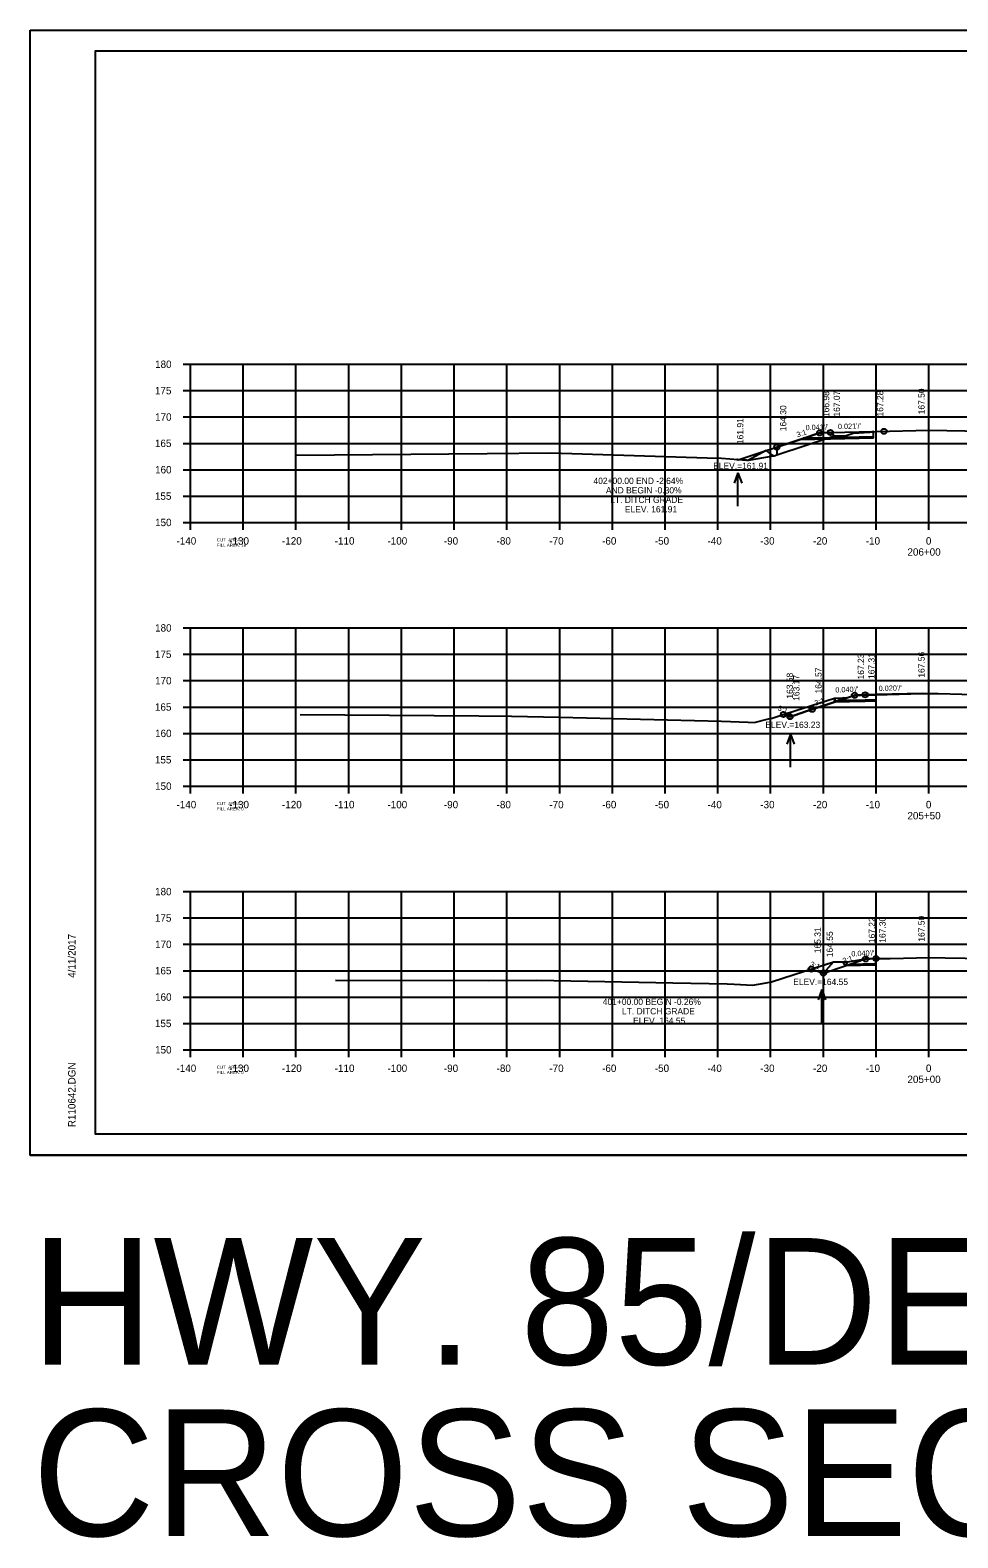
# Model space of a CAD drawing. Extents: x 1368503 to 1373085, y 379840 to 381833.
# Drawn here: x 1368502.7 to 1368678.6, y 379840.1 to 380126 of the extents above; entities that cross this region are included whole.
import ezdxf

# ---------------------------------------------------------------- set-up
doc = ezdxf.new("R2010")
doc.units = 0
for name, color, linetype in [('S_BRIDGE', 7, 'Continuous'), ('S_EDGE_PAVEMENT', 7, 'Continuous'), ('S_GRAVEL_ROAD', 7, 'Continuous'), ('S_MISC_BOUNDARY', 7, 'Continuous'), ('S_OBSCURES', 7, 'Continuous'), ('S_PHOTO_CENTERS', 7, 'Continuous'), ('S_PHOTO_NOTES', 7, 'Continuous'), ('S_RDW_PT_SYM', 7, 'Continuous'), ('S_SHOULDER', 7, 'Continuous'), ('S_STREAM_ANNOT', 7, 'Continuous'), ('S_TRAILS', 7, 'Continuous'), ('S_TRAILS_ANNOT', 7, 'Continuous'), ('S_TREE', 7, 'Continuous')]:
    doc.layers.add(name, color=color, linetype=linetype)

msp = doc.modelspace()

# ---------------------------------------------------------------- linework, layer by layer
at = {"layer": 'S_BRIDGE'}
for p, q in [((1368515.06, 380122.15), (1368831.24, 380122.15)), ((1368515.06, 379916.69), (1368515.06, 380122.15)), ((1368667.58, 380121.89), (1368667.58, 380121.89)), ((1368667.58, 380121.89), (1368667.58, 380121.89)), ((1368515.06, 379916.69), (1368515.06, 379916.69)), ((1368831.24, 379916.69), (1368515.06, 379916.69))]:
    msp.add_line(p, q, dxfattribs=at)
at = {"layer": 'S_EDGE_PAVEMENT'}
for p, q in [((1368531.66, 380062.69), (1368533.06, 380062.69)), ((1368533.06, 380032.69), (1368533.06, 380062.69)), ((1368531.66, 380057.69), (1368533.06, 380057.69)), ((1368531.66, 380052.69), (1368533.06, 380052.69)), ((1368531.66, 380047.69), (1368533.06, 380047.69)), ((1368531.66, 380042.69), (1368533.06, 380042.69)), ((1368531.66, 380037.69), (1368533.06, 380037.69)), ((1368531.66, 380032.69), (1368533.06, 380032.69)), ((1368533.06, 380032.69), (1368813.06, 380032.69)), ((1368533.06, 380031.29), (1368533.06, 380032.69)), ((1368543.06, 380031.29), (1368543.06, 380032.69)), ((1368553.06, 380031.29), (1368553.06, 380032.69)), ((1368563.06, 380031.29), (1368563.06, 380032.69)), ((1368573.06, 380031.29), (1368573.06, 380032.69)), ((1368583.06, 380031.29), (1368583.06, 380032.69)), ((1368593.06, 380031.29), (1368593.06, 380032.69)), ((1368603.06, 380031.29), (1368603.06, 380032.69)), ((1368613.06, 380031.29), (1368613.06, 380032.69)), ((1368623.06, 380031.29), (1368623.06, 380032.69)), ((1368633.06, 380031.29), (1368633.06, 380032.69)), ((1368643.06, 380031.29), (1368643.06, 380032.69)), ((1368653.06, 380031.29), (1368653.06, 380032.69)), ((1368663.06, 380031.29), (1368663.06, 380032.69)), ((1368673.06, 380031.29), (1368673.06, 380032.69)), ((1368531.66, 380012.69), (1368533.06, 380012.69)), ((1368533.06, 379982.69), (1368533.06, 380012.69)), ((1368531.66, 380007.69), (1368533.06, 380007.69)), ((1368531.66, 380002.69), (1368533.06, 380002.69)), ((1368531.66, 379997.69), (1368533.06, 379997.69)), ((1368531.66, 379992.69), (1368533.06, 379992.69)), ((1368531.66, 379987.69), (1368533.06, 379987.69)), ((1368531.66, 379982.69), (1368533.06, 379982.69)), ((1368533.06, 379982.69), (1368813.06, 379982.69)), ((1368533.06, 379981.29), (1368533.06, 379982.69)), ((1368543.06, 379981.29), (1368543.06, 379982.69)), ((1368553.06, 379981.29), (1368553.06, 379982.69)), ((1368563.06, 379981.29), (1368563.06, 379982.69)), ((1368573.06, 379981.29), (1368573.06, 379982.69)), ((1368583.06, 379981.29), (1368583.06, 379982.69)), ((1368593.06, 379981.29), (1368593.06, 379982.69)), ((1368603.06, 379981.29), (1368603.06, 379982.69)), ((1368613.06, 379981.29), (1368613.06, 379982.69)), ((1368623.06, 379981.29), (1368623.06, 379982.69)), ((1368633.06, 379981.29), (1368633.06, 379982.69)), ((1368643.06, 379981.29), (1368643.06, 379982.69)), ((1368653.06, 379981.29), (1368653.06, 379982.69)), ((1368663.06, 379981.29), (1368663.06, 379982.69)), ((1368673.06, 379981.29), (1368673.06, 379982.69)), ((1368531.66, 379962.69), (1368533.06, 379962.69)), ((1368533.06, 379932.69), (1368533.06, 379962.69)), ((1368531.66, 379957.69), (1368533.06, 379957.69)), ((1368531.66, 379952.69), (1368533.06, 379952.69)), ((1368531.66, 379947.69), (1368533.06, 379947.69)), ((1368531.66, 379942.69), (1368533.06, 379942.69)), ((1368531.66, 379937.69), (1368533.06, 379937.69)), ((1368531.66, 379932.69), (1368533.06, 379932.69)), ((1368533.06, 379932.69), (1368813.06, 379932.69)), ((1368533.06, 379931.29), (1368533.06, 379932.69)), ((1368543.06, 379931.29), (1368543.06, 379932.69)), ((1368553.06, 379931.29), (1368553.06, 379932.69)), ((1368563.06, 379931.29), (1368563.06, 379932.69)), ((1368573.06, 379931.29), (1368573.06, 379932.69)), ((1368583.06, 379931.29), (1368583.06, 379932.69)), ((1368593.06, 379931.29), (1368593.06, 379932.69)), ((1368603.06, 379931.29), (1368603.06, 379932.69)), ((1368613.06, 379931.29), (1368613.06, 379932.69)), ((1368623.06, 379931.29), (1368623.06, 379932.69)), ((1368633.06, 379931.29), (1368633.06, 379932.69)), ((1368643.06, 379931.29), (1368643.06, 379932.69)), ((1368653.06, 379931.29), (1368653.06, 379932.69)), ((1368663.06, 379931.29), (1368663.06, 379932.69)), ((1368673.06, 379931.29), (1368673.06, 379932.69))]:
    msp.add_line(p, q, dxfattribs=at)
at = {"layer": 'S_GRAVEL_ROAD'}
for p, q in [((1368636.87, 380042.08), (1368636.17, 380040.15)), ((1368636.87, 380035.79), (1368636.87, 380042.08)), ((1368636.87, 380042.08), (1368637.57, 380040.15)), ((1368646.8, 379992.54), (1368646.1, 379990.62)), ((1368646.8, 379986.26), (1368646.8, 379992.54)), ((1368646.8, 379992.54), (1368647.5, 379990.62)), ((1368652.75, 379944.11), (1368652.05, 379942.19)), ((1368652.75, 379937.83), (1368652.75, 379944.11)), ((1368652.75, 379944.11), (1368653.45, 379942.19))]:
    msp.add_line(p, q, dxfattribs=at)
at = {"layer": 'S_MISC_BOUNDARY'}
for points in [[(1368553.12, 380045.44), (1368589.33, 380045.77), (1368601.36, 380045.92), (1368631, 380044.95), (1368633.74, 380044.86), (1368638.49, 380044.53), (1368638.85, 380044.51), (1368638.86, 380044.51), (1368643.63, 380045.32), (1368643.71, 380045.34), (1368644.22, 380045.51), (1368655.16, 380049.14), (1368656.51, 380049.12), (1368657.09, 380049.12), (1368657.26, 380049.13), (1368657.4, 380049.18), (1368658.68, 380049.59), (1368661.9, 380049.83), (1368662.56, 380049.9), (1368663.09, 380049.91), (1368673.13, 380050.19), (1368683.23, 380050)], [(1368553.88, 379996.27), (1368587.76, 379996.01), (1368593.95, 379995.98), (1368603.01, 379995.75), (1368633.77, 379995), (1368638.78, 379994.83), (1368639.91, 379994.78), (1368642.67, 379995.43), (1368643.32, 379995.56), (1368646.23, 379996.52), (1368655.15, 379999.36), (1368656.88, 379999.44), (1368657.38, 379999.44), (1368658.46, 379999.73), (1368658.94, 379999.85), (1368660.17, 379999.91), (1368662.95, 380000.02), (1368671.95, 380000.23), (1368673.36, 380000.26), (1368674.81, 380000.23), (1368683.78, 380000.03)], [(1368560.55, 379945.87), (1368589.57, 379945.84), (1368598.71, 379945.87), (1368624.54, 379945.37), (1368634.81, 379945.2), (1368636.13, 379945.13), (1368639.7, 379944.97), (1368642.21, 379945.41), (1368643.23, 379945.56), (1368647.5, 379946.94), (1368655.01, 379949.38), (1368656.69, 379949.37), (1368657.63, 379949.36), (1368659.94, 379949.75), (1368660.37, 379949.83), (1368660.89, 379949.85), (1368663.01, 379949.98), (1368665.73, 379950.03), (1368673.22, 379950.19), (1368676.14, 379950.14), (1368683.74, 379949.99)]]:
    msp.add_lwpolyline(points, dxfattribs=at)
at = {"layer": 'S_OBSCURES'}
for points in [[(1368662.56, 380048.68), (1368654.4, 380048.51), (1368648.44, 380048.38)], [(1368662.56, 380048.93), (1368654.4, 380048.76), (1368649.25, 380048.65)], [(1368663.06, 379998.8), (1368660.98, 379998.75), (1368655.09, 379998.64)], [(1368663.06, 379999.05), (1368660.98, 379999), (1368655.89, 379998.9)], [(1368663.01, 379948.74), (1368657.2, 379948.62)], [(1368663.01, 379948.99), (1368658, 379948.89)]]:
    msp.add_lwpolyline(points, dxfattribs=at)
at = {"layer": 'S_PHOTO_CENTERS'}
for p, q in [((1368533.06, 380062.69), (1368813.06, 380062.69)), ((1368533.06, 380032.69), (1368533.06, 380062.69)), ((1368543.06, 380032.69), (1368543.06, 380062.69)), ((1368553.06, 380032.69), (1368553.06, 380062.69)), ((1368563.06, 380032.69), (1368563.06, 380062.69)), ((1368573.06, 380032.69), (1368573.06, 380062.69)), ((1368583.06, 380032.69), (1368583.06, 380062.69)), ((1368593.06, 380032.69), (1368593.06, 380062.69)), ((1368603.06, 380032.69), (1368603.06, 380062.69)), ((1368613.06, 380032.69), (1368613.06, 380062.69)), ((1368623.06, 380032.69), (1368623.06, 380062.69)), ((1368633.06, 380032.69), (1368633.06, 380062.69)), ((1368643.06, 380032.69), (1368643.06, 380062.69)), ((1368653.06, 380032.69), (1368653.06, 380062.69)), ((1368663.06, 380032.69), (1368663.06, 380062.69)), ((1368673.06, 380032.69), (1368673.06, 380062.69)), ((1368533.06, 380057.69), (1368813.06, 380057.69)), ((1368533.06, 380052.69), (1368813.06, 380052.69)), ((1368533.06, 380047.69), (1368813.06, 380047.69)), ((1368533.06, 380042.69), (1368813.06, 380042.69)), ((1368533.06, 380037.69), (1368813.06, 380037.69)), ((1368533.06, 380032.69), (1368813.06, 380032.69)), ((1368533.06, 380012.69), (1368813.06, 380012.69)), ((1368533.06, 379982.69), (1368533.06, 380012.69)), ((1368543.06, 379982.69), (1368543.06, 380012.69)), ((1368553.06, 379982.69), (1368553.06, 380012.69)), ((1368563.06, 379982.69), (1368563.06, 380012.69)), ((1368573.06, 379982.69), (1368573.06, 380012.69)), ((1368583.06, 379982.69), (1368583.06, 380012.69)), ((1368593.06, 379982.69), (1368593.06, 380012.69)), ((1368603.06, 379982.69), (1368603.06, 380012.69)), ((1368613.06, 379982.69), (1368613.06, 380012.69)), ((1368623.06, 379982.69), (1368623.06, 380012.69)), ((1368633.06, 379982.69), (1368633.06, 380012.69)), ((1368643.06, 379982.69), (1368643.06, 380012.69)), ((1368653.06, 379982.69), (1368653.06, 380012.69)), ((1368663.06, 379982.69), (1368663.06, 380012.69)), ((1368673.06, 379982.69), (1368673.06, 380012.69)), ((1368533.06, 380007.69), (1368813.06, 380007.69)), ((1368533.06, 380002.69), (1368813.06, 380002.69)), ((1368533.06, 379997.69), (1368813.06, 379997.69)), ((1368533.06, 379992.69), (1368813.06, 379992.69)), ((1368533.06, 379987.69), (1368813.06, 379987.69)), ((1368533.06, 379982.69), (1368813.06, 379982.69)), ((1368533.06, 379962.69), (1368813.06, 379962.69)), ((1368533.06, 379932.69), (1368533.06, 379962.69)), ((1368543.06, 379932.69), (1368543.06, 379962.69)), ((1368553.06, 379932.69), (1368553.06, 379962.69)), ((1368563.06, 379932.69), (1368563.06, 379962.69)), ((1368573.06, 379932.69), (1368573.06, 379962.69)), ((1368583.06, 379932.69), (1368583.06, 379962.69)), ((1368593.06, 379932.69), (1368593.06, 379962.69)), ((1368603.06, 379932.69), (1368603.06, 379962.69)), ((1368613.06, 379932.69), (1368613.06, 379962.69)), ((1368623.06, 379932.69), (1368623.06, 379962.69)), ((1368623.06, 379932.69), (1368623.06, 379962.69)), ((1368623.06, 379932.69), (1368623.06, 379962.69)), ((1368633.06, 379932.69), (1368633.06, 379962.69)), ((1368643.06, 379932.69), (1368643.06, 379962.69)), ((1368653.06, 379932.69), (1368653.06, 379962.69)), ((1368663.06, 379932.69), (1368663.06, 379962.69)), ((1368673.06, 379932.69), (1368673.06, 379962.69)), ((1368533.06, 379957.69), (1368813.06, 379957.69)), ((1368533.06, 379952.69), (1368813.06, 379952.69)), ((1368533.06, 379947.69), (1368813.06, 379947.69)), ((1368533.06, 379942.69), (1368813.06, 379942.69)), ((1368533.06, 379937.69), (1368813.06, 379937.69)), ((1368533.06, 379932.69), (1368813.06, 379932.69))]:
    msp.add_line(p, q, dxfattribs=at)
at = {"layer": 'S_PHOTO_NOTES'}
for p, q in [((1368502.66, 380126.04), (1368835.99, 380126.04)), ((1368502.66, 379912.71), (1368835.99, 379912.71))]:
    msp.add_line(p, q, dxfattribs=at)
for points in [[(1368502.65, 380126.04), (1368835.99, 380126.04), (1368835.99, 379912.71), (1368502.65, 379912.71)], [(1368748.98, 380122.15), (1368748.98, 380112.27), (1368784.71, 380112.27), (1368784.71, 380109.35), (1368807.91, 380109.35), (1368807.91, 380085.02), (1368831.24, 380085.02), (1368831.24, 379916.69), (1368515.06, 379916.69), (1368515.06, 380122.15)], [(1368644.22, 380045.51), (1368655.16, 380049.14), (1368654.4, 380049.76), (1368652.7, 380049.69), (1368652.37, 380049.67), (1368649.22, 380048.64), (1368648.44, 380048.38), (1368647.51, 380048.07), (1368644.23, 380046.99)], [(1368661.9, 380049.83), (1368662.56, 380049.9), (1368662.56, 380049.93)], [(1368638.86, 380044.51), (1368643.63, 380045.32), (1368642.22, 380046.33)], [(1368636.71, 380044.65), (1368636.71, 380044.66), (1368638.49, 380044.53), (1368636.92, 380044.58)], [(1368646.23, 379996.52), (1368655.15, 379999.36), (1368655.09, 379998.64), (1368651.44, 379997.43), (1368650.93, 379997.26), (1368647.49, 379996.11), (1368646.73, 379995.86)], [(1368655.15, 379999.36), (1368656.88, 379999.44), (1368655.47, 379998.76)], [(1368658.94, 379999.85), (1368660.17, 379999.91), (1368658.97, 379999.92)], [(1368660.17, 379999.91), (1368662.95, 380000.02), (1368661.58, 380000.02), (1368660.98, 380000), (1368660.85, 380000)], [(1368662.95, 380000.02), (1368671.95, 380000.23), (1368663.06, 380000.05)], [(1368645.49, 379996.27), (1368645.49, 379996.28), (1368646.23, 379996.52), (1368645.59, 379996.24)], [(1368650.77, 379948), (1368655.01, 379949.38), (1368653.06, 379947.24), (1368653.06, 379947.24)], [(1368656.69, 379949.37), (1368657.63, 379949.36), (1368657.2, 379948.62)], [(1368660.89, 379949.85), (1368663.01, 379949.98), (1368663.01, 379949.99), (1368661.06, 379949.91)]]:
    msp.add_lwpolyline(points, close=True, dxfattribs=at)
for centre in [(1368652.37, 380049.67), (1368654.4, 380049.76), (1368664.57, 380049.97), (1368644.23, 380046.99), (1368658.97, 379999.92), (1368660.98, 380000), (1368645.49, 379996.27), (1368646.73, 379995.86), (1368650.93, 379997.26), (1368650.77, 379948), (1368653.06, 379947.24), (1368653.06, 379947.24), (1368661.06, 379949.91), (1368663.06, 379949.99)]:
    msp.add_circle(centre, 0.5, dxfattribs=at)
at = {"layer": 'S_STREAM_ANNOT'}
for points in [[(1368636.71, 380044.65), (1368636.92, 380044.58), (1368642.22, 380046.33), (1368644.23, 380046.99), (1368647.51, 380048.07), (1368648.44, 380048.38), (1368649.22, 380048.64), (1368652.37, 380049.67), (1368652.7, 380049.69), (1368654.4, 380049.76), (1368662.56, 380049.93)], [(1368645.49, 379996.27), (1368645.59, 379996.24), (1368646.73, 379995.86), (1368647.49, 379996.11), (1368650.93, 379997.26), (1368651.44, 379997.43), (1368655.09, 379998.64), (1368655.47, 379998.76), (1368658.97, 379999.92), (1368660.85, 380000), (1368660.98, 380000), (1368661.58, 380000.02), (1368663.06, 380000.05)], [(1368650.77, 379948), (1368653.06, 379947.24), (1368653.06, 379947.24), (1368657.2, 379948.62), (1368661.06, 379949.91), (1368663.01, 379949.99)]]:
    msp.add_lwpolyline(points, dxfattribs=at)
at = {"layer": 'S_TREE'}
for p, q in [((1368662.56, 380048.68), (1368662.56, 380049.9)), ((1368663.06, 379998.8), (1368663.06, 380000.02)), ((1368663.01, 379948.74), (1368663.01, 379949.99))]:
    msp.add_line(p, q, dxfattribs=at)

# ---------------------------------------------------------------- texts
at = {"layer": 'S_BRIDGE'}
for s, p in [('4/11/2017', (1368511.25, 379946.33)), ('R110642.DGN', (1368511.25, 379918.01))]:
    msp.add_text(s, height=1.4, rotation=90, dxfattribs=at).set_placement(p)
at = {"layer": 'S_GRAVEL_ROAD'}
for s, p in [('ELEV.=161.91', (1368632.16, 380042.81)), ('402+00.00 END -2.64%', (1368609.47, 380039.99)), ('AND BEGIN -0.30%', (1368611.82, 380038.19)), ('LT. DITCH GRADE', (1368612.64, 380036.39)), ('ELEV. 161.91', (1368615.42, 380034.59)), ('ELEV.=163.23', (1368642.06, 379993.72)), ('ELEV.=164.55', (1368647.34, 379944.97)), ('401+00.00 BEGIN -0.26%', (1368611.23, 379941.2)), ('LT. DITCH GRADE', (1368614.87, 379939.4)), ('ELEV. 164.55', (1368616.97, 379937.6))]:
    msp.add_text(s, height=1.2, dxfattribs=at).set_placement(p)
at = {"layer": 'S_PHOTO_NOTES'}
for s, p in [('HWY. 85/DETOUR', (1368502.86, 379872.99)), ('CROSS SECTIONS', (1368503.08, 379840.48))]:
    msp.add_text(s, height=24, dxfattribs=at).set_placement(p)
at = {"layer": 'S_RDW_PT_SYM'}
for s, rotation, p in [("0.041'/'", 2.3504, (1368649.71, 380050.17)), ("0.021'/'", 1.2228, (1368655.83, 380050.39)), ('3:1', 18.2359, (1368648.14, 380048.81)), ('3:1', 18.3635, (1368651.56, 379997.93)), ("0.040'/'", 2.2888, (1368655.35, 380000.43)), ("0.020'/'", 1.149, (1368663.55, 380000.72)), ('3:1', 341.8835, (1368644.33, 379997.09)), ("0.040'/'", 2.2906, (1368658.39, 379950.4)), ('3:1', 341.5668, (1368650.45, 379948.53)), ('3:1', 18.4349, (1368656.9, 379949.05))]:
    msp.add_text(s, height=1, rotation=rotation, dxfattribs=at).set_placement(p)
at = {"layer": 'S_SHOULDER'}
for s, p in [('166.98', (1368654.17, 380052.67)), ('167.07', (1368656.2, 380052.76)), ('167.28', (1368664.41, 380052.78)), ('164.30', (1368646.03, 380049.99)), ('161.91', (1368637.88, 380047.55)), ('167.23', (1368660.77, 380002.92)), ('167.31', (1368662.78, 380003)), ('164.57', (1368652.73, 380000.26)), ('163.58', (1368647.29, 379999.27)), ('163.17', (1368648.53, 379998.86)), ('167.22', (1368662.86, 379952.91)), ('167.30', (1368664.86, 379952.99)), ('165.31', (1368652.57, 379951)), ('164.55', (1368654.86, 379950.24)), ('164.55', (1368654.86, 379950.24))]:
    msp.add_text(s, height=1.2, rotation=90, dxfattribs=at).set_placement(p)
at = {"layer": 'S_TRAILS'}
for s, height, p in [('180', 1.4, (1368526.34, 380061.99)), ('175', 1.4, (1368526.31, 380056.99)), ('170', 1.4, (1368526.34, 380051.99)), ('165', 1.4, (1368526.31, 380046.99)), ('160', 1.4, (1368526.34, 380041.99)), ('155', 1.4, (1368526.31, 380036.99)), ('150', 1.4, (1368526.34, 380031.99)), ('-140', 1.4, (1368530.4, 380028.49)), ('CUT  AREA: 0', 0.6, (1368538.06, 380029.09)), ('FILL AREA: 18', 0.6, (1368538.06, 380028.09)), ('-130', 1.4, (1368540.4, 380028.49)), ('-120', 1.4, (1368550.4, 380028.49)), ('-110', 1.4, (1368560.4, 380028.49)), ('-100', 1.4, (1368570.4, 380028.49)), ('-90', 1.4, (1368581.1, 380028.49)), ('-80', 1.4, (1368591.1, 380028.49)), ('-70', 1.4, (1368601.1, 380028.49)), ('-60', 1.4, (1368611.1, 380028.49)), ('-50', 1.4, (1368621.1, 380028.49)), ('-40', 1.4, (1368631.1, 380028.49)), ('-30', 1.4, (1368641.1, 380028.49)), ('-20', 1.4, (1368651.1, 380028.49)), ('-10', 1.4, (1368661.1, 380028.49)), ('206+00', 1.4, (1368669, 380026.39)), ('0', 1.4, (1368672.5, 380028.49)), ('180', 1.4, (1368526.34, 380011.99)), ('175', 1.4, (1368526.31, 380006.99)), ('170', 1.4, (1368526.34, 380001.99)), ('165', 1.4, (1368526.31, 379996.99)), ('160', 1.4, (1368526.34, 379991.99)), ('155', 1.4, (1368526.31, 379986.99)), ('150', 1.4, (1368526.34, 379981.99)), ('-140', 1.4, (1368530.4, 379978.49)), ('CUT  AREA: 7', 0.6, (1368538.06, 379979.09)), ('-130', 1.4, (1368540.4, 379978.49)), ('-120', 1.4, (1368550.4, 379978.49)), ('-110', 1.4, (1368560.4, 379978.49)), ('-100', 1.4, (1368570.4, 379978.49)), ('-90', 1.4, (1368581.1, 379978.49)), ('-80', 1.4, (1368591.1, 379978.49)), ('-70', 1.4, (1368601.1, 379978.49)), ('-60', 1.4, (1368611.1, 379978.49)), ('-50', 1.4, (1368621.1, 379978.49)), ('-40', 1.4, (1368631.1, 379978.49)), ('-30', 1.4, (1368641.1, 379978.49)), ('-20', 1.4, (1368651.1, 379978.49)), ('-10', 1.4, (1368661.1, 379978.49)), ('0', 1.4, (1368672.5, 379978.49)), ('FILL AREA: 0', 0.6, (1368538.06, 379978.09)), ('205+50', 1.4, (1368669, 379976.39)), ('180', 1.4, (1368526.34, 379961.99)), ('175', 1.4, (1368526.31, 379956.99)), ('170', 1.4, (1368526.34, 379951.99)), ('165', 1.4, (1368526.31, 379946.99)), ('160', 1.4, (1368526.34, 379941.99)), ('155', 1.4, (1368526.31, 379936.99)), ('150', 1.4, (1368526.34, 379931.99)), ('-140', 1.4, (1368530.4, 379928.49)), ('CUT  AREA: 4', 0.6, (1368538.06, 379929.09)), ('FILL AREA: 0', 0.6, (1368538.06, 379928.09)), ('-130', 1.4, (1368540.4, 379928.49)), ('-120', 1.4, (1368550.4, 379928.49)), ('-110', 1.4, (1368560.4, 379928.49)), ('-100', 1.4, (1368570.4, 379928.49)), ('-90', 1.4, (1368581.1, 379928.49)), ('-80', 1.4, (1368591.1, 379928.49)), ('-70', 1.4, (1368601.1, 379928.49)), ('-60', 1.4, (1368611.1, 379928.49)), ('-50', 1.4, (1368621.1, 379928.49)), ('-40', 1.4, (1368631.1, 379928.49)), ('-30', 1.4, (1368641.1, 379928.49)), ('-20', 1.4, (1368651.1, 379928.49)), ('-10', 1.4, (1368661.1, 379928.49)), ('205+00', 1.4, (1368669, 379926.39)), ('0', 1.4, (1368672.5, 379928.49))]:
    msp.add_text(s, height=height, dxfattribs=at).set_placement(p)
at = {"layer": 'S_TRAILS_ANNOT'}
for s, p in [('167.50', (1368672.26, 380053.19)), ('167.56', (1368672.26, 380003.25)), ('167.50', (1368672.26, 379953.19))]:
    msp.add_text(s, height=1.2, rotation=90, dxfattribs=at).set_placement(p)

doc.saveas('drawing.dxf')
